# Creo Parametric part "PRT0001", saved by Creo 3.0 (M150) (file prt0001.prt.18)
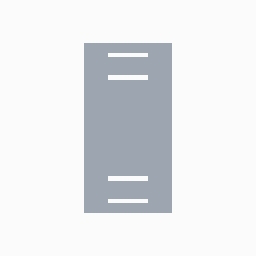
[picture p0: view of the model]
Units: millimeter Newton Second (mmNs); MM, TONNE, SECS

Created from: INLBS_PART_SOLID.PRT

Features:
  1. datum plane "RIGHT"
  2. datum plane "TOP"
  3. datum plane "FRONT"
  4. coordinate system
  5. sketch "Sketch 1"
  6. sketch "Sketch 2"
  7. extrusion "Extrude 1"
  8. extruded cut "Extrude 2"

Surfaces: 25 plane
